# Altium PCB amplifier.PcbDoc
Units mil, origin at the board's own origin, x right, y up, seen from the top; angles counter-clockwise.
Board outline 473.22 x 1259.84 mil, 2 copper layers (Top Layer, Bottom Layer); 25 components, 19 nets, 69 pads, 12 vias.
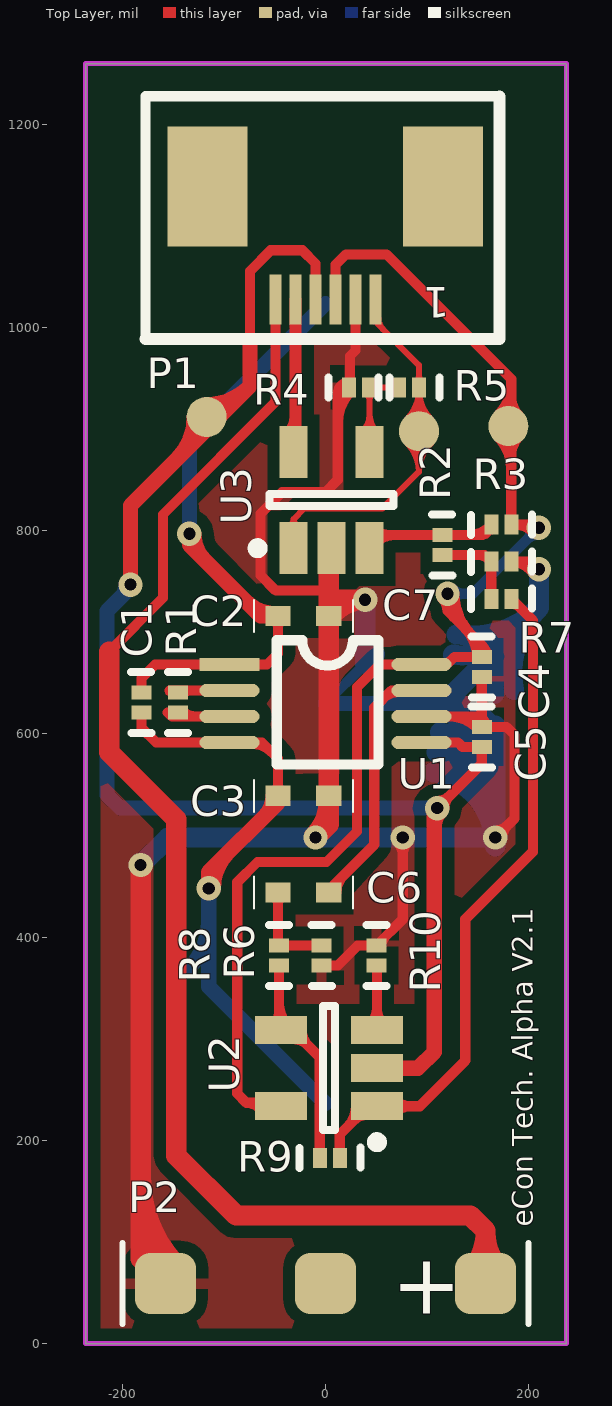
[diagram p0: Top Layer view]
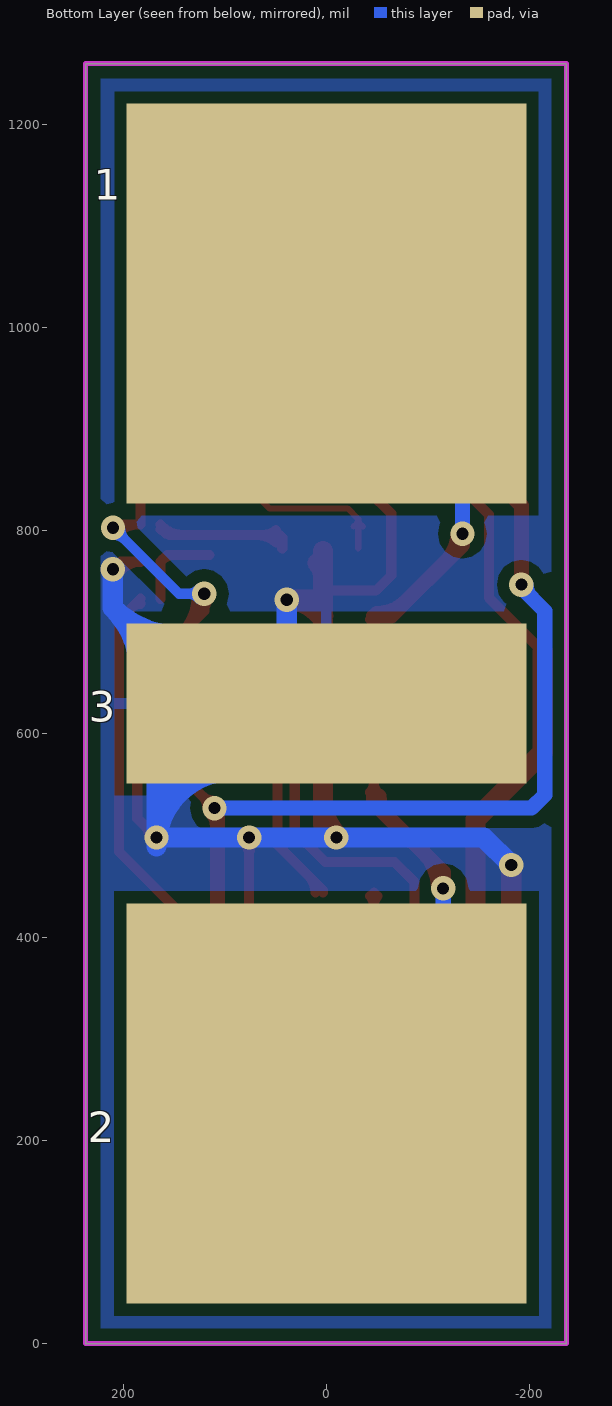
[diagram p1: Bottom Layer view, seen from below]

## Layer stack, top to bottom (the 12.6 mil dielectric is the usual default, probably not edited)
Top Layer: signal copper 1.4
Dielectric: dielectric 12.6, FR-4, Dk 4.8
Bottom Layer: signal copper 1.4

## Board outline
-236.22,0 237,0 237,1259.84 -236.22,1259.84

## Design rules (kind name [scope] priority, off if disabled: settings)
AssemblyTestPointUsage [All] p1 off:
AssemblyTestpoint [All] p1 off: testpointundercomponent=TRUE minsize=40 maxsize=100 preferedsize=60 minholesize=0 maxholesize=40 preferedholesize=32 testpointgrid=1 usegrid=TRUE gridtolerance=0.01 allowsidetop=TRUE allowsidebottom=TRUE
Clearance Clearance_1 [InPolygon] p1: gap=12
Clearance [All] p2: gap=5
ComponentClearance [All] p1 off: gap=10 collisioncheckmode=3 verticalgap=10 showdistances=FALSE
DiffPairsRouting [All] p1 off: maxlimit=10 minlimit=10 mostfreqgap=10 maxuncoupledlength=500
FabricationTestPointUsage [All] p1 off: valid=0 allowmultiple=FALSE
FabricationTestpoint [All] p1 off: side=3 testpointundercomponent=TRUE minsize=40 maxsize=100 preferedsize=60 minholesize=0 maxholesize=40 preferedholesize=32 testpointgrid=1 allowsidetop=TRUE allowsidebottom=TRUE usegrid=TRUE gridtolerance=0.01
FanoutControl Fanout_BGA [IsBGA] p1 off: bgadir=Out bgaviamode=Centered fanoutstyle=Auto fanoutdirection=Alternating viagrid=1 // Fanout_BGA (Default Rule)
FanoutControl Fanout_LCC [IsLCC] p2 off: bgadir=Out bgaviamode=Centered fanoutstyle=Auto fanoutdirection=Alternating viagrid=1 // Fanout_LCC (Default Rule)
FanoutControl Fanout_SOIC [IsSOIC] p3 off: bgadir=Out bgaviamode=Centered fanoutstyle=Auto fanoutdirection=Alternating viagrid=1 // Fanout_SOIC (Default Rule)
FanoutControl Fanout_Small [(CompPinCount < 5)] p4 off: bgadir=Out bgaviamode=Centered fanoutstyle=Auto fanoutdirection=OutThenIn viagrid=1 // Fanout_Small (Default Rule)
FanoutControl Fanout_Default [All] p5 off: bgadir=Out bgaviamode=Centered fanoutstyle=Auto fanoutdirection=Alternating viagrid=1 // Fanout_Default (Default Rule)
Height [All] p1 off: minheight=0 maxheight=1000 prefheight=500
HoleSize [All] p1 off: absolutevalues=TRUE maxlimit=100 minlimit=1 maxpercent=80.000 minpercent=20.000
HoleToHoleClearance [All] p1 off: gap=10 allowstackedmicrovias=TRUE
LayerPairs [All] p1 off: enforce=TRUE
MinimumSolderMaskSliver [All] p1 off: minsoldermaskwidth=10
NetAntennae [All] p1 off: netantennaetolerance=0
PasteMaskExpansion [All] p1 off: expansion=0
PlaneClearance [All] p1 off: clearance=20
PlaneConnect [All] p1 off: planeconnectstyle=Relief reliefexpansion=20 reliefentries=4 reliefconductorwidth=10 reliefairgap=10
PolygonConnect PolygonConnect_1 [(InPadClass('All Pads'))] p1: connectstyle=Relief reliefconductorwidth=10 reliefentries=4 polygonreliefangle="90 Angle"
PolygonConnect [All] p2: connectstyle=Direct reliefconductorwidth=10 reliefentries=4 polygonreliefangle="90 Angle"
RoutingCorners [All] p1 off: cornerstyle=45-Degree minsetback=100 maxsetback=100
RoutingLayers [All] p1 off: top layer_v5=TRUE bottom layer_v5=TRUE
RoutingPriority [All] p1 off: routingpriority=0
RoutingTopology [All] p1 off: topology=Shortest
RoutingVias [All] p1: holewidth=12 width=24 viastyle="Through Hole" minholewidth=12 minwidth=24 maxholewidth=12 maxwidth=24
SilkToSilkClearance [All] p1 off: silktosilkclearance=10
SilkscreenOverComponentPads [All] p1 off: minsilkscreentomaskgap=10
SolderMaskExpansion [All] p1 off: expansion=4
Width [All] p1: maxlimit=20 minlimit=6 preferedwidth=6
2 further rules are at their usual default settings.

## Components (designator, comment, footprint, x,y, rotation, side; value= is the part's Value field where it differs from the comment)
1 "Electrode" elec-diff 0,1023.62 r270 bottom locked
2 "Electrode" elec-diff 0,236.22 r270 bottom locked
3 "Electrode" elec-ref 0,629.92 r270 bottom locked
C1 "" 0201 -181.22,631 r90 top
C2 "" "0402 - MI" -46.78,716 r0 top
C3 "" "0402 - MI" 3.22,539 r180 top
C4 "Cap" 0201 153.78,666 r270 top
C5 "Cap" 0201 153.78,597 r270 top
C6 "" "0402 - MI" -46.78,443.84 r0 top
C7 "" 0201 173,769.5 r180 top
P1 "Header 6" "6P_0.5mm(FPC) - duplicate" 49.21,1027.56 r180 top locked
P2 "Header 3" BAT3 0,59.06 r0 top locked (schematic designator P3)
R1 "4.42k" 0201 -145.22,631 r270 top
R2 "10K" 0201 115,786 r90 top
R3 "10K" 0201 173,806 r180 top
R4 "10K" 0201 33.16,941 r180 top
R5 "10K" 0201 82.09,941 r180 top
R6 "2.7K" 0201 -3.78,381.84 r90 top
R7 "1K" 0201 173,733 r180 top
R8 "1K" 0201 -45.78,381.84 r270 top
R9 "10K" 0201 4.22,182.84 r0 top
R10 "2.7K" 0201 50.22,381.84 r270 top
U1 "AD8236" MSOP-8 0,629.92 r0 top locked
U2 "AD8603" SOT23-5AM 3.32,271 r180 top
U3 "AD8603" SOT23-5AM 6,830 r90 top locked

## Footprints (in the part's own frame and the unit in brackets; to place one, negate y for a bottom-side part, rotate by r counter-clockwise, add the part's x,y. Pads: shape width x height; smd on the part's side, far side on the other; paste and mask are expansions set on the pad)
"6P_0.5mm(FPC) - duplicate" [mm]
  rect 2x3 smd: 0(-1.69,-2.825) 7(4.2,-2.825)
  rect 0.3x1.25 smd mask+0.051: 1(0,0) 2(0.5,0) 3(1,0) 4(1.5,0) 5(2,0) 6(2.5,0)
  silkscreen extent -3.1,-5.08 5.75,0.99
0201 [mm]
  rect 0.35x0.5 smd: 1(-0.25,0) 2(0.25,0)
  silkscreen extent -0.76,-0.25 0.76,0.25
"0402 - MI" [mil]
  rect 25x20 smd: 1(0,0) 2(50,0)
  silkscreen extent -24,-16 74,16
BAT3 [mil]
  rrect50% 60x60 smd: 1(-157.48,0) 2(0,0) 3(157.48,0)
  silkscreen extent -200,-40 200,40
elec-diff [mm] "12*5mm"
  rect 10x10 smd: 1(0,0)
elec-ref [mm] "12*5mm"
  rect 4x10 smd: 1(0,0)
MSOP-8 [mm]
  rect 1.5x0.325 smd: 1(-2.4,0.975)
  oval 1.5x0.325 smd: 2(-2.4,0.325) 3(-2.4,-0.325) 4(-2.4,-0.975) 5(2.4,-0.975) 6(2.4,-0.325) 7(2.4,0.325) 8(2.4,0.975)
  silkscreen extent -1.22,-1.52 1.32,1.58
SOT23-5AM [mm] "SOT23, 5-Leads, Body 2.9x1.7mm, Pitch 0.95mm, Lead Span 2.8mm, IPC Low Density"
  rect 1.3x0.7 smd: 1(-1.2,0.95) 2(-1.2,0) 3(-1.2,-0.95) 4(1.2,-0.95) 5(1.2,0.95)
  silkscreen extent -1.33,-1.55 0.15,1.97, body extent -0.9,-1.55 0.9,1.55, height 1.45

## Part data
C1 C2 C3 C6 C7: library part Cap, "Capacitor"
C4 C5: "Capacitor"
P1: "Header, 6-Pin"
P2: "Header, 3-Pin"
R1 R2 R3 R4 R5 R6 R7 R8 R9 R10: library part Res2, "Resistor"
U1: library part INA128UA, "Precision, Low-Power Instrumentation Amplifiers"

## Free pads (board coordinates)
  round 39.37 smd: 0(92,898) 1(180,903) 2(-117,912)

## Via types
v1: diameter 24, hole 12, Top Layer to Bottom Layer, tented both sides, 9 vias
v2: diameter 24, hole 12, Top Layer to Bottom Layer, 3 vias

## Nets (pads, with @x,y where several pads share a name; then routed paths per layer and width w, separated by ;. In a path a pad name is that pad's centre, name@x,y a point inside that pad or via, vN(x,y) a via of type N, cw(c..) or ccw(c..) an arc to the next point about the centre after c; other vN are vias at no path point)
+3.3V: P1.5 U3.5 | length 180.6
  Top Layer w6: U3.5 U3.5@-29.53,879.12
  Top Layer w12: U3.5@-36.9,894.56 ccw(c-54.71,912.36) -29.53,912.36 ; U3.5@-29.53,879.12 P1.5 ; -29.53,903.31 ccw(c-17.14,903.31) U3.5@-25.9,894.56
+3.7V: P1.6 P2.3 | length 1400.6
  Top Layer w10: -213,681 -160,734 -160,816 -49.21,926.79 P1.6
  Top Layer w20: -213,681 -213,582.09 -146.91,516 -146.91,184.91 -88,126 142.48,126 157.48,111 P2.3 ; P2.3@143.34,73.2 ccw(c109.2,107.34) 157.48,107.34 ccw(c205.76,107.34) P2.3@171.62,73.2
+VS: C4.1 P1.3 pad.1 R3.1 U1.8 U2.5 | length 1659.7
  Top Layer w10: U2.5@-63.15,228.89 ccw(c-77.9,219.52) -77.9,237 ; U2.5 -47.33,237 -77.91,237 ; P1.3 9.84,1061.75 20.09,1072 60.09,1072 182.84,949.25 R3.1 205.09,806 210,801.09 v1(210,803) ; v1@115.14,733.05 cw(c103.19,721.1) 120.09,721.1 cw(c136.99,721.1) v1@125.04,733.05 ; v1@117.09,738 ccw(c150.89,738) 126.99,714.1 ; U1.8@117.62,669.7 ccw(c117.62,677.38) 123.05,671.95 ; v1(120.09,738) 120.09,721 153.78,687.32 C4.1 126.94,675.84 119.4,668.31 U1.8 53.31,668.31 31,646 31,504 1,474 -66.91,474 -86.91,454 -86.91,246 -77.91,237 ; v1@127.09,738 ccw(c185.04,738) 144.07,697.03 ; 137.4,703.69 cw(c109.55,675.84) C4.1@148.94,675.84 ; 154.47,686.62 cw(c143.69,675.84) C4.1@158.94,675.84 ; pad.1@169.62,892.62 cw(c137.68,860.68) 182.84,860.68 ; pad.1@169.62,913.38 ccw(c137.68,945.32) 182.84,945.32 ; 182.84,874.41 cw(c208.59,874.41) pad.1@190.38,892.62 ; 182.84,931.59 ccw(c208.59,931.59) pad.1@190.38,913.38 ; R3.1@185.86,806 cw(c185.86,778.86) v1@205.05,798.05
  Bottom Layer w10: v1(120.09,738) 145,738 205,798 213.09,798 210,801.09 v1(210,803) ; v1@125.04,733.05 cw(c136.99,721.1) 136.99,738 cw(c136.99,754.9) v1@125.04,742.95 ; v1@203,803 cw(c186.1,803) 198.05,791.05 cw(c210,779.1) v1@210,796
-VS: C5.2 P1.4 pad.2 U1.5 U2.2 | length 1634.6
  Top Layer w10: -74.41,985 -74.41,1055.5 -53.91,1076 -22.91,1076 -9.84,1062.94 P1.4 ; U1.5 130.56,591.54 135.09,587 C5.2@153.62,587 ; v1@107.09,524 153.78,570.68 C5.2 ; v1@110,534 ccw(c110,551.13) 122.11,539.02 ; v1@117,527 cw(c133.67,527) 121.88,538.79
  Top Layer w15: v2(-192,747) -192,824.91 -74.41,942.5 -74.41,985 ; -146.35,870.55 ccw(c-187.8,912) pad.2@-129.19,912 ; pad.2@-117,924.18 ccw(c-117,982.8) -75.55,941.35 ; U2.2 91.09,271 107.09,287 v1@107.09,524 ; U2.2@66.81,266.56 cw(c77.53,255.84) 77.53,271 cw(c77.53,286.16) U2.2@66.81,275.44 ; 107.09,509.12 cw(c127.88,509.12) v1@113.18,523.82
  Bottom Layer w15: -201.8,734.2 ccw(c-214.61,747) v2@-196.5,747 ; v2(-192,747) -192,744 -215,721 -215,540 -202,527 v1(110,527)
GND: 3.1 C2.2 C3.1 C4.2 C5.1 C7.1 P1.2 P2.1 R4.2 R6.1 R10.1 U1.6 U3.2 | length 4004.4
  Top Layer w10: R6.1 12.09,372 31.78,391.68 R10.1 76,417.46 v1(76,498) ; C2.2@-1.91,716 C2.2@3.22,710.87 ; 3.22,732 C2.2 3.22,741 -48.91,741 -63.91,756 -63.91,817 -42.91,838 0,838 12.09,850.09 12.09,929.78 R4.2 24.09,941.78 24.09,972 29.53,977.43 P1.2 ; U3.2@3.22,779.98 U3.2 ; 12.09,906.4 cw(c54.97,906.4) R4.2@24.65,936.71 ; 12.09,924.11 cw(c24.17,924.11) R4.2@23.43,936.16 ; 12.09,930.54 cw(c30.82,930.54) R4.2@17.58,943.78 ; 12.09,934.74 cw(c23.52,934.74) R4.2@22.82,946.14 ; 15.05,932.73 cw(c23.32,924.47) R4.2@23.32,936.16 ; R10.1@55.06,391.68 cw(c66.75,391.68) 58.49,399.95 ; v1@71.05,493.05 cw(c59.1,481.1) 76,481.1 cw(c92.9,481.1) v1@80.95,493.05 ; U1.6 143.5,617.13 C5.1 ; U1.6@121.44,617.13 cw(c121.44,577.45) C5.1@149.49,605.51 ; 145.51,615.11 cw(c137.25,606.84) C5.1@148.94,606.84 ; 145.58,617.13 cw(c145.58,601.6) C5.1@156.56,612.58 ; C4.2 C5.1 ; v1@167.09,504 173.09,504 186.09,517 186.09,599 178.25,606.84 C5.1 ; v1@167.09,505 ccw(c167.09,521.9) 179.04,509.95 ccw(c190.99,498) v1@174.09,498 ; v1@204.29,758.09 ccw(c182.84,743.64) C7.1 202.59,769.5 v1(210.09,762) ; 3.22,728.07 ccw(c15.29,728.07) 6.76,719.54 cw(c15.29,728.07) 3.22,728.07 ; 3.22,728.07 cw(c-8.85,728.07) -0.32,719.54 ccw(c-8.85,728.07) 3.22,728.07
  Top Layer w20: -182,118.25 ccw(c-98.28,118.25) P2.1 -182,83.57 v2(-182,471) ; -182,166.54 ccw(c-50,166.54) P2.1@-143.34,73.2 ; v1@-11.32,499.41 ccw(c-46.42,534.52) C3.1@3.22,534.52 ; v1(-9.91,498) 3.22,511.13 C3.1 C2.2@3.22,710.87 ; C2.2 U3.2@3.22,779.98 ; 3.22,732 v1(39,732) ccw(c39,689.39) C2.2@5.72,716 ; 3.22,755.11 cw(c21.83,755.11) U3.2@8.67,768.27
  Bottom Layer w10: 3.1@39,668.92 3.1 3.1@115.92,629.92
  Bottom Layer w15: 3.1 145.08,629.92 3.1@167.09,607.91
  Bottom Layer w20: v2(-182,471) -155,498 ; -105,498 -155,498 ; 3.1@39,668.92 v1(39,732) ; 3.1@39,701.72 ccw(c71.8,701.72) 3.1@48.61,678.53 ; 3.1@105.98,562.26 cw(c92.87,489.2) v1@167.09,489.2 ; 3.1@109.51,581.95 cw(c97.16,513.11) 167.09,513.11 ; 3.1@113.04,601.63 cw(c101.45,537.02) 167.09,537.02 ; 3.1@115.92,629.92 210.09,724.09 ; 3.1@116.57,621.32 cw(c105.74,560.92) 3.1@167.09,560.92 ; 3.1@125.81,678.05 ccw(c136.14,742.64) 3.1@182.39,696.39 ; 3.1@128.97,697.8 ccw(c143.78,790.41) 210.09,724.09 ; 3.1@165.92,639.39 cw(c229.27,651.94) 3.1@183.61,697.61 ; 3.1@167.09,607.91 v1(167.09,498) v1(76,498) v1(-9.91,498) -155,498 ; 3.1@185.54,643.28 cw(c273.48,660.7) 210.09,724.09 ; v1(210.09,762) 210.09,724.09
Net1_1: 1.1 C1.2 C2.1 U1.1 | length 685.3
  Top Layer w10: C1.2 -181.22,654.78 -167.69,668.31 U1.1 -57.6,668.31 -46.78,679.13 C2.1 ; C2.1@-50.32,712.46 cw(c-58.85,703.93) -46.78,703.93 cw(c-34.71,703.93) C2.1@-43.24,712.46
  Top Layer w15: v2(-134,797) -134,786.09 -63.91,716 C2.1 ; v2@-129.5,797 ccw(c-92.31,797) -118.61,770.7 ; -78.52,730.61 ccw(c-49.28,759.85) C2.1@-49.28,718.5
  Bottom Layer w15: v2(-134,797) -134,889.62 1.1
Net2_1: 2.1 C1.1 C3.2 U1.4 | length 727.6
  Top Layer w10: C1.1 -181.22,606.22 -166.54,591.54 U1.4 -62.54,591.54 -46.78,575.78 C3.2 ; U1.4@-71.36,590.14 cw(c-71.36,565.46) -53.91,582.91 ; C3.2@-50.32,542.54 ccw(c-58.85,551.07) -46.78,551.07 ccw(c-34.71,551.07) C3.2@-43.24,542.54
  Top Layer w15: v1(-115,448) -115,463.91 -46.78,532.13 C3.2 ; v1@-110.5,448 cw(c-61.24,448) -96.07,482.83 ; -60.18,518.73 ccw(c-80.45,539) C3.2@-51.78,539
  Bottom Layer w15: 2.1@-133.89,370.11 ccw(c-179.5,415.72) 2.1@-115,415.72 ; v1(-115,448) -115,351.22 2.1
NetC6_1: C6.1 R6.2 R8.1 | length 119.8
  Top Layer w10: C6.1@-50.32,440.31 cw(c-58.85,431.77) -46.78,431.77 cw(c-34.71,431.77) C6.1@-43.24,440.31 ; -46.78,398.66 ccw(c-38.8,398.66) R8.1@-44.44,393.02 ; C6.1 -46.78,392.68 R8.1 R6.2
NetC6_2: C6.2 U1.7 | length 287.9
  Top Layer w10: C6.2 3.22,446.22 48,491 48,625.91 64.81,642.72 U1.7 ; C6.2@10.72,443.84 cw(c34.57,443.84) 17.71,460.71 ; 57.8,635.7 cw(c71.36,622.14) U1.7@71.36,641.32
NetC7_2: C7.2 R2.1 R7.2 | length 100.9
  Top Layer w10: R2.1 156.5,776.16 C7.2 R7.2 ; 149.65,776.16 cw(c149.65,758.95) C7.2@161.82,771.12
NetR1_1: R1.1 U1.2 | length 70.1
  Top Layer w6: -155.22,640.84 R1.1@-153.35,642.72
  Top Layer w10: R1.1@-153.35,642.72 U1.2 ; R1.1@-140.93,639.51 cw(c-133.18,631.76) -133.18,642.72
NetR1_2: R1.2 U1.3 | length 76.8
  Top Layer w10: -155.22,621.16 -151.19,617.13 U1.3 ; R1.2@-140.93,622.49 ccw(c-127.97,635.45) -127.97,617.13
NetR2_2: R2.2 R3.2 U3.3 | length 213.2
  Top Layer w10: U3.3 43.4,793.4 45.84,795.84 R2.2 153,795.84 ; U3.3@49.61,788.36 cw(c67.68,770.29) 67.68,795.84 ; U3.3@49.61,800.77 ccw(c61.52,812.68) 61.52,795.84 ; 141.2,795.84 ccw(c141.2,825) R3.2@161.82,804.38 ; 154.89,797.73 cw(c163.16,789.47) R3.2@163.16,801.16 ; R3.2@161.28,803.26 cw(c153,804.17) 153,795.84 ; R3.2 153,795.84
NetR4_1: R4.1 R5.2 U3.4 | length 178.3
  Top Layer w6: U3.4@35.78,896.68 ccw(c17.38,915.08) 43.4,915.08 ccw(c69.43,915.08) U3.4@51.02,896.68 ; R4.1@40.25,935.3 cw(c32.64,927.69) 43.4,927.69 ; U3.4 43.4,940.6 R4.1 R5.2 ; 43.4,929.63 cw(c51.42,929.63) R4.1@45.75,935.3 ; R4.1@45.75,938.25 cw(c52.39,931.61) 52.39,941 cw(c52.39,950.39) R4.1@45.75,943.75 ; R5.2@69.5,938.25 ccw(c62.86,931.61) 62.86,941 ccw(c62.86,950.39) R5.2@69.5,943.75
NetR7_1: R7.1 R9.2 U2.1 | length 743.1
  Top Layer w6: U2.1@42,233.6 U2.1
  Top Layer w10: R9.2 14.06,205.66 U2.1@42,233.6 ; 21.46,213.06 ccw(c0.92,233.6) U2.1@29.97,233.6 ; U2.1@29.31,220.91 cw(c38.75,211.47) U2.1@38.75,224.82 ; U2.1 92.69,233.6 137.55,278.45 137.55,417.55 204.09,484.09 204.09,711.75 R7.1 ; U2.1@68.58,227.39 cw(c83.57,212.4) 83.57,233.6 cw(c83.57,254.79) U2.1@68.58,239.81 ; R7.1@182.84,728.16 cw(c182.84,716.47) 191.11,724.73
NetR8_2: R8.2 R9.1 U2.4 | length 279.1
  Top Layer w6: U2.4@-45.78,318 -45.78,310.25 U2.4
  Top Layer w10: U2.4@-50.14,314.61 ccw(c-60.66,325.13) -45.78,325.13 ; U2.4@-45.78,318 R8.2 ; -45.78,334.06 ccw(c-18.27,334.06) U2.4@-37.72,314.61 ; U2.4 -32.4,308.4 -5.62,281.62 R9.1 ; U2.4@-32.12,299.62 cw(c-32.12,279.11) -17.61,293.61 ; U2.4@-23.34,308.4 ccw(c-1.46,308.4) -16.93,292.93
NetR10_2: R10.2 U2.3 | length 97
  Top Layer w6: R10.2 R10.2@50.56,371.66
  Top Layer w10: U2.3@44.35,314.61 ccw(c29.36,329.6) 50.56,329.6 ccw(c71.75,329.6) U2.3@56.77,314.61 ; U2.3 R10.2@50.56,371.66
NTC3: P2.2
VOUT: P1.1 pad.0 R5.1 U3.1 | length 624.6
  Top Layer w6: U3.1@-35.97,804.33 ccw(c-39.32,811.5) -31.4,811.5 ; U3.1 -31.4,811.5 ; U3.1@-26.84,804.33 cw(c-23.49,811.5) -31.4,811.5 ; P1.1 49.21,1005.54 91.94,962.82 R5.1 91.94,857.94 ; P1.1@52.12,1008.84 ccw(c67.09,1008.84) 56.5,998.25 ; pad.0@80.22,886.19 cw(c52.04,857.94) 91.94,857.94 ; pad.0@80.2,909.8 ccw(c51.87,938.13) R5.1@91.94,938.13 ; pad.0@84.44,905.56 ccw(c66.36,923.64) 91.94,923.64 ; pad.0@84.45,890.44 cw(c66.46,872.4) 91.94,872.4 ; R5.1@89.19,935.3 cw(c82.55,928.66) 91.94,928.66 cw(c101.33,928.66) R5.1@94.69,935.3 ; R5.1@89.19,946.7 ccw(c82.55,953.34) 91.94,953.34 ccw(c101.33,953.34) R5.1@94.69,946.7 ; 91.94,872.29 cw(c117.37,872.29) pad.0@99.51,890.4 ; 91.94,923.95 ccw(c117.95,923.95) pad.0@99.56,905.56 ; R5.1@91.94,938.43 ccw(c132.43,938.43) pad.0@103.8,909.8 ; pad.0@103.72,886.12 ccw(c131.54,857.94) 91.94,857.94 ; -31.4,811.5 -20.91,822 56,822 91.94,857.94
pads on no net: P1.0 P1.7

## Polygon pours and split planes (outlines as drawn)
GND on Bottom Layer "Top Layer-No Net" (solid, remove dead copper, pour order 4): -222,1315 391,1315 391,1142 391,-55 -299,-55 -494,-55 -494,92 -494,1335 -449,1335
GND on Top Layer "Top Layer-No Net" (solid, remove dead copper, pour order 2): -353,1309 317,1309 317,1021 317,-27 -301,-27

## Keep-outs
Keep-Out Layer:
  lines w5: 236.22,0 -236.22,0 -236.22,1259.84 236.22,1259.84 ; 237,0 237,1259.84

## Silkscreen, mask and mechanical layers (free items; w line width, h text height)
Top Overlay:
  text "eCon Tech. Alpha V2.1" at 204,115 h20 r90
